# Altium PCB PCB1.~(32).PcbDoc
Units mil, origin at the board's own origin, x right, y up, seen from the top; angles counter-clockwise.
Board outline 4773 x 3993 mil, 2 copper layers (Top Layer, Bottom Layer); 27 components, 21 nets, 91 pads, 0 vias.
Unrouted connection lines stored in the file: 51.
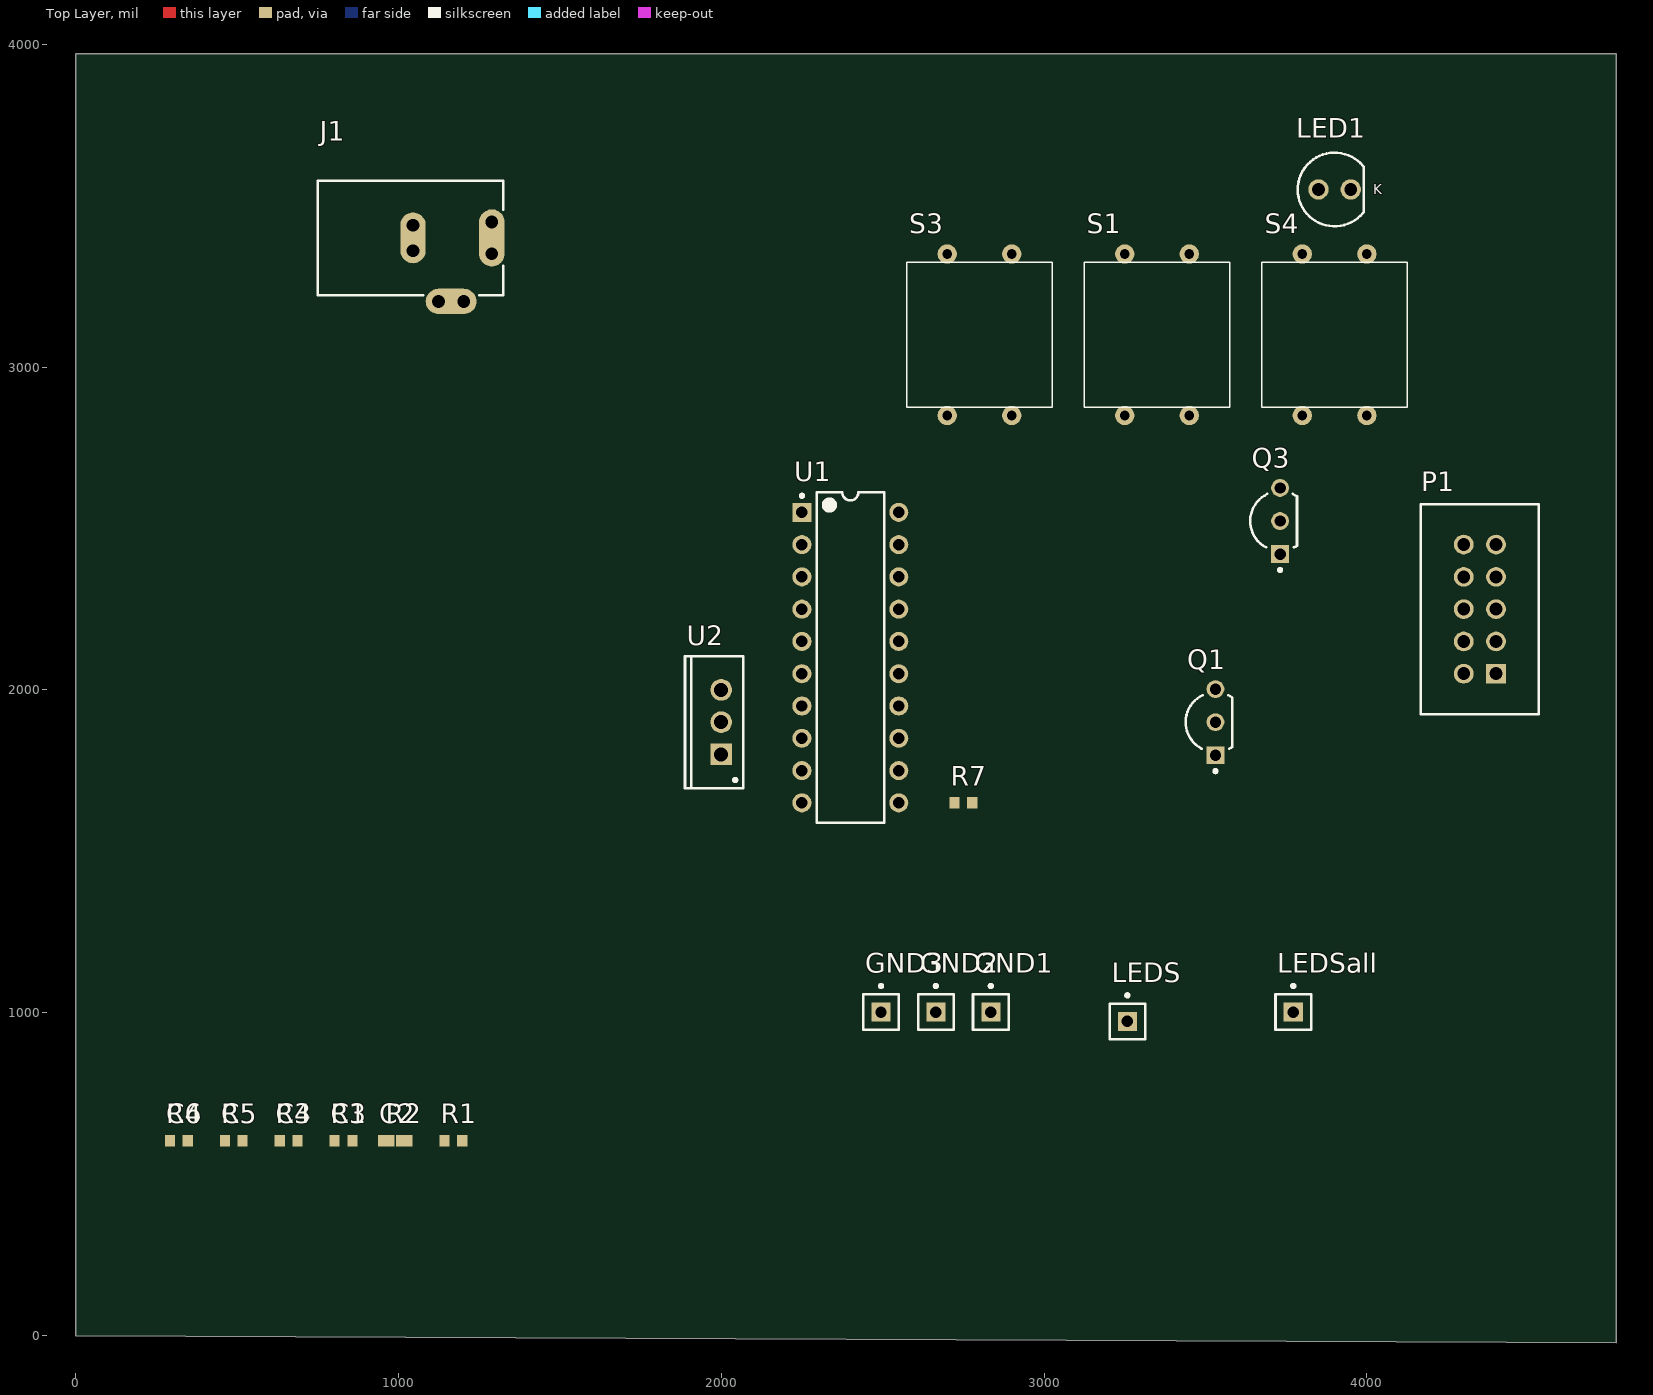
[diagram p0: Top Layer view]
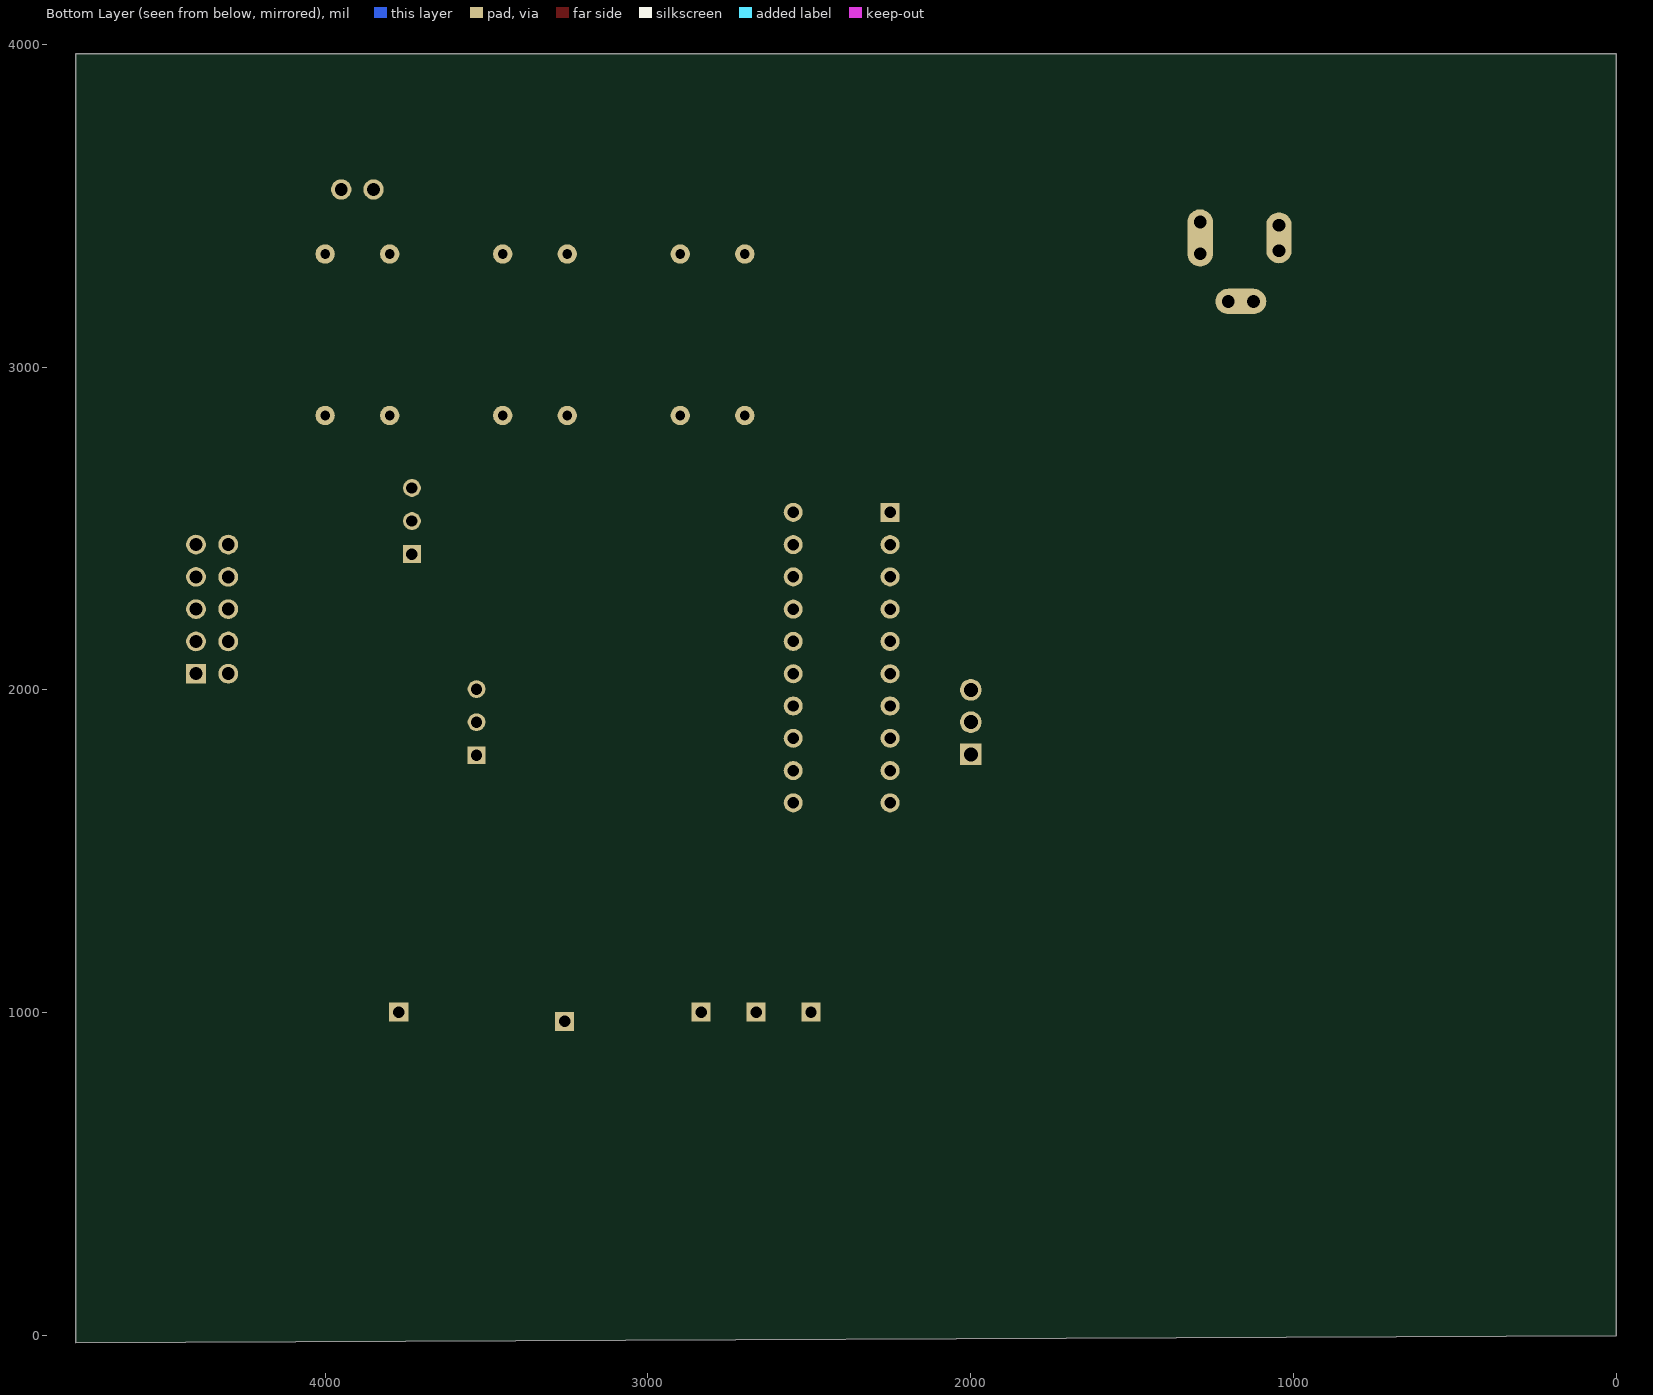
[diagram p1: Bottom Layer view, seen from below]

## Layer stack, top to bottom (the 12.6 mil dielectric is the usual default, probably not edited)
Top Solder: solder mask 0.4, Solder Resist, Dk 3.5
Top Layer: signal copper 1.4
Dielectric 1: dielectric 12.6, FR-4, Dk 4.8
Bottom Layer: signal copper 1.4
Bottom Solder: solder mask 0.4, Solder Resist, Dk 3.5

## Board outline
0,0 0,3971 4368,3971 4773,3971 4773,-22

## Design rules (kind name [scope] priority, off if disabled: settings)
Clearance Clearance_U1_1 [InComponent('U1') vs IsRegion] p1: gap=10
Clearance Clearance_U1 [InComponent('U1') vs OnLayer('Top Layer')] p2: gap=7
Clearance [All] p3: gap=10
MinimumSolderMaskSliver [All] p1 off: minsoldermaskwidth=10
PasteMaskExpansion [All] p1 off: expansion=0
PolygonConnect [All] p1: connectstyle=Relief reliefconductorwidth=10 reliefentries=4 polygonreliefangle="90 Angle" airgapwidth=10
RoutingVias [All] p1: holewidth=28 width=50 viastyle="Through Hole" minholewidth=10 minwidth=20 maxholewidth=30 maxwidth=50
SolderMaskExpansion [All] p1 off: expansion=4
Width [All] p1: maxlimit=20 minlimit=10 preferedwidth=10
28 further rules are at their usual default settings.

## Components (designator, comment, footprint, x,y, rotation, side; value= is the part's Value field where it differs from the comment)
C1 "Cap Semi" CAPC1608L 830,604 r0 top
C2 "Cap Semi" CAPC1608L 980,604 r0 top
C3 "Cap Semi" CAPC1608L 660,604 r0 top
C4 "Cap Semi" CAPC1608L 320,604 r0 top
C5 "Cap Semi" CAPC1608L 490,604 r0 top
GND1 "GNDout" PIN1 2835,1002 r0 top
GND2 "GNDout" PIN1 2665,1002 r0 top
GND3 "GNDout" PIN1 2495,1002 r0 top
J1 "PWR2.5" KLD-0202 750,3400 r0 top
LED1 "151051YS04000" "Type 5mm" 3900,3550 r0 top
LEDS "uleds" PIN1 3258,973 r0 top
LEDSall "uleds_all" PIN1 3772,1002 r0 top
P1 "ZSS-105-01-F-D-450" SMTC-ZSS-105-01-X-D-450 4400,2050 r90 top
Q1 "2N5551" ONSC-TO-92-3-29-11_AM_BL 3531,1900 r90 top
Q3 "2N5551" ONSC-TO-92-3-29-11_AM_BL 3731,2523 r90 top
R1 "Res3" CAPC1608L 1170,604 r0 top
R2 "Res3" CAPC1608L 1000,604 r0 top
R3 "Res3" CAPC1608L 830,604 r0 top
R4 "Res3" CAPC1608L 660,604 r0 top
R5 "Res3" CAPC1608L 490,604 r0 top
R6 "Res3" CAPC1608L 320,604 r0 top
R7 "Res3" CAPC1608L 2750,1650 r0 top
S1 "START_min" key 3350,3100 r180 top
S3 "START_all" key 2800,3100 r180 top
S4 "PAUSE" key 3900,3100 r180 top
U1 "ATtiny2313V-10PU" 20P3 2400,2100 r0 top
U2 "MC78M05CTG" TO220 2000,1900 r90 top

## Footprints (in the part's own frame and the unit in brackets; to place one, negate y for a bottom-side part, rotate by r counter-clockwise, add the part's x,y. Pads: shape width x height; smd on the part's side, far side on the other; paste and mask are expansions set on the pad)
20P3 [mm] "DIP, 20-Pin, Row Spacing 7.62 mm, Pitch 2.54 mm"
  rect 1.5x1.5 hole 0.9: 1(-3.81,11.43)
  round 1.5 hole 0.9: 2(-3.81,8.89) 3(-3.81,6.35) 4(-3.81,3.81) 5(-3.81,1.27) 6(-3.81,-1.27) 7(-3.81,-3.81) 8(-3.81,-6.35) 9(-3.81,-8.89) 10(-3.81,-11.43) 11(3.81,-11.43) 12(3.81,-8.89) 13(3.81,-6.35) 14(3.81,-3.81) 15(3.81,-1.27) 16(3.81,1.27) 17(3.81,3.81) 18(3.81,6.35) 19(3.81,8.89) 20(3.81,11.43)
  silkscreen extent -3.93,-13 2.65,13, body extent -3.6,-12.95 3.6,12.95, height 5.08
CAPC1608L [mm] "Chip Capacitor, Body 1.6x0.8mm, IPC High Density"
  rect 0.8x0.9 smd: 1(-0.7,0) 2(0.7,0)
  body extent -0.87,-0.48 0.87,0.48, height 1.3
key [mil]
  round 60 hole 30: 1(100,-250) 2(-100,-250) 3(-100,250) 4(100,250)
  silkscreen extent -225,-225 225,225, body extent -250,-250 250,250, height 470
KLD-0202 [mm] "DC Power Jack, 2.5mm, KLD Series, PCB Mount"
  oval 2x4.5 all layers, no hole: 1(13.7,0)
  round 1.5 hole 1: 1A(13.7,-1.25) 1B(13.7,1.25) 2A(7.5,-1) 2B(7.5,1) 3A(9.5,-5) 3B(11.5,-5)
  oval 2x4 all layers, no hole: 2(7.5,0)
  oval 4x2 all layers, no hole: 3(10.5,-5)
  silkscreen extent 0,-4.5 14.6,4.5
ONSC-TO-92-3-29-11_AM_BL [mm] "TO, 3-Leads, Body Dia 4.7mm, Pitch 2.6mm"
  rect 1.4x1.4 hole 0.9: 1(-2.6,0)
  round 1.4 hole 0.9: 2(0,0) 3(2.6,0)
  silkscreen extent -3.97,-1.34 2.13,2.35, body extent -2.84,-1.34 2.84,2.35, height 5.33
PIN1 [mm] "Connector; Plug"
  rect 1.5x1.5 hole 0.9: 1(0,0)
  silkscreen extent -1.4,-1.4 1.4,2.17
SMTC-ZSS-105-01-X-D-450 [mm] "Shrouded .025\" SQ Post Header, 2x5 Pins, Vertical, 2.54mm Pitch, Male"
  rect 1.55x1.55 hole 1.02: 1(0,0)
  round 1.55 hole 1.02: 2(0,2.54) 3(2.54,0) 4(2.54,2.54) 5(5.08,0) 6(5.08,2.54) 7(7.62,0) 8(7.62,2.54) 9(10.16,0) 10(10.16,2.54)
  silkscreen extent -3.18,-3.36 13.33,5.9, body extent -3.17,-3.57 13.34,5.91, height 11.43
TO220 [mm] "TO, Thru-Hole, Vertical, Heatsink Mounted; 3 In-Line Leads; Pitch 2.54 mm"
  rect 1.7x1.7 hole 1.1: 1(-2.54,0)
  round 1.7 hole 1.1: 2(0,0) 3(2.54,0)
  silkscreen extent -5.2,-1.75 5.2,2.85, body extent -5.25,-1.8 5.25,2.9, height 19.7
"Type 5mm" [mm] "THT, LED-5mm, 2pin- Body 5.8mm"
  round 1.6 hole 1: 1(1.27,0) 2(-1.27,0)
  silkscreen extent -2.9,-2.9 2.29,2.9, body extent -2.9,-2.9 2.5,2.9, height 11.7

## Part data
C1 C2 C3 C4 C5: "Capacitor (Semiconductor SIM Model)"
GND1 GND2 GND3 LEDS LEDSall: library part Plug, "Plug"
J1: "Low Voltage Power Supply Connector"
LED1: library part CMP-1488-00010-1, "THT LED round mono-color color lens, WL-TMRW, Yellow"
P1: library part CMP-1024-00461-1
Q1 Q3: library part CMP-1048-01479-1, "Amplifier Transistor, NPN Silicon, 3-Pin TO-92, Pb-Free, Tape and Reel"
R1 R2 R3 R4 R5 R6 R7: "Resistor"
S1 S3 S4: library part SW-DPST, "Double-Pole, Single-Throw Switch"
U1: library part CMP-0093-00017-1, "Low Power tinyAVR® 8-Bit Microcontroller, 2K Flash Memory, 10MHz, Industrial Temperature, 20-Lead PDIP, Pb-Free"
U2: library part CMP-0244-00483-1, "Positive Voltage Regulator, 5V, 3-Pin TO-220"

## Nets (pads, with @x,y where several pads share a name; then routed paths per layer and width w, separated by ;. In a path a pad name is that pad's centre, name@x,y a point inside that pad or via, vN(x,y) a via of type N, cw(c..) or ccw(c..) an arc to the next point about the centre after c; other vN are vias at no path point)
+24V: C4.2 J1.1 J1.1A J1.1B Q1.3 Q3.3 U2.1
BUT_PAUSE: R3.2 S4.1 U1.14
BUT_START: R1.2 S1.1 U1.12
BUT_STARTALL: R2.2 S3.1 U1.13
GND: C1.1 C2.1 C3.2 C4.1 C5.1 GND1.1 GND2.1 GND3.1 J1.3 J1.3A J1.3B LED1.1 P1.4 P1.6 P1.8 P1.10 S1.2 S3.2 S4.2 U1.10 U2.2
MISO: P1.9 U1.18
MOSI: P1.1 U1.17
NetC1_2: C1.2 U1.4
NetC2_2: C2.2 U1.5
NetJ1_2: J1.2 J1.2A J1.2B
NetLED1_2: LED1.2 R7.2
NetLEDS_1: LEDS.1 Q1.1
NetLEDSall_1: LEDSall.1 Q3.1
NetQ1_2: Q1.2 R5.2
NetQ3_2: Q3.2 R6.2
NetR7_1: R7.1 U1.11
RES: C3.1 P1.5 R4.2 U1.1
SCK: P1.7 U1.19
ULEDS: R5.1 U1.15
ULEDSALL: R6.1 U1.16
VCC: C5.2 P1.2 R1.1 R2.1 R3.1 R4.1 U1.20 U2.3
pads on no net: P1.3 S1.3 S1.4 S3.3 S3.4 S4.3 S4.4 U1.2 U1.3 U1.6 U1.7 U1.8 U1.9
